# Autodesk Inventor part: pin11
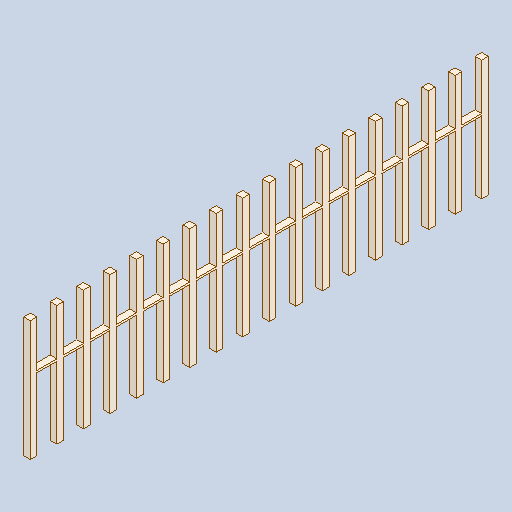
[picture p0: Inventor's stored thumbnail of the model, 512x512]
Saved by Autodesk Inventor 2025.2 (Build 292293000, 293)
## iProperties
Created: 2025-04
Part Number: pin11
Material: Generic
Description: PART--DESC
Document SubType Name: Modeling
Designer: BennF
Density: 1 g/cm^3
Appearance: Default
Author: BennF
Revision Number: NONE
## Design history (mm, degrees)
feature "Solid"
body "Solid1"
